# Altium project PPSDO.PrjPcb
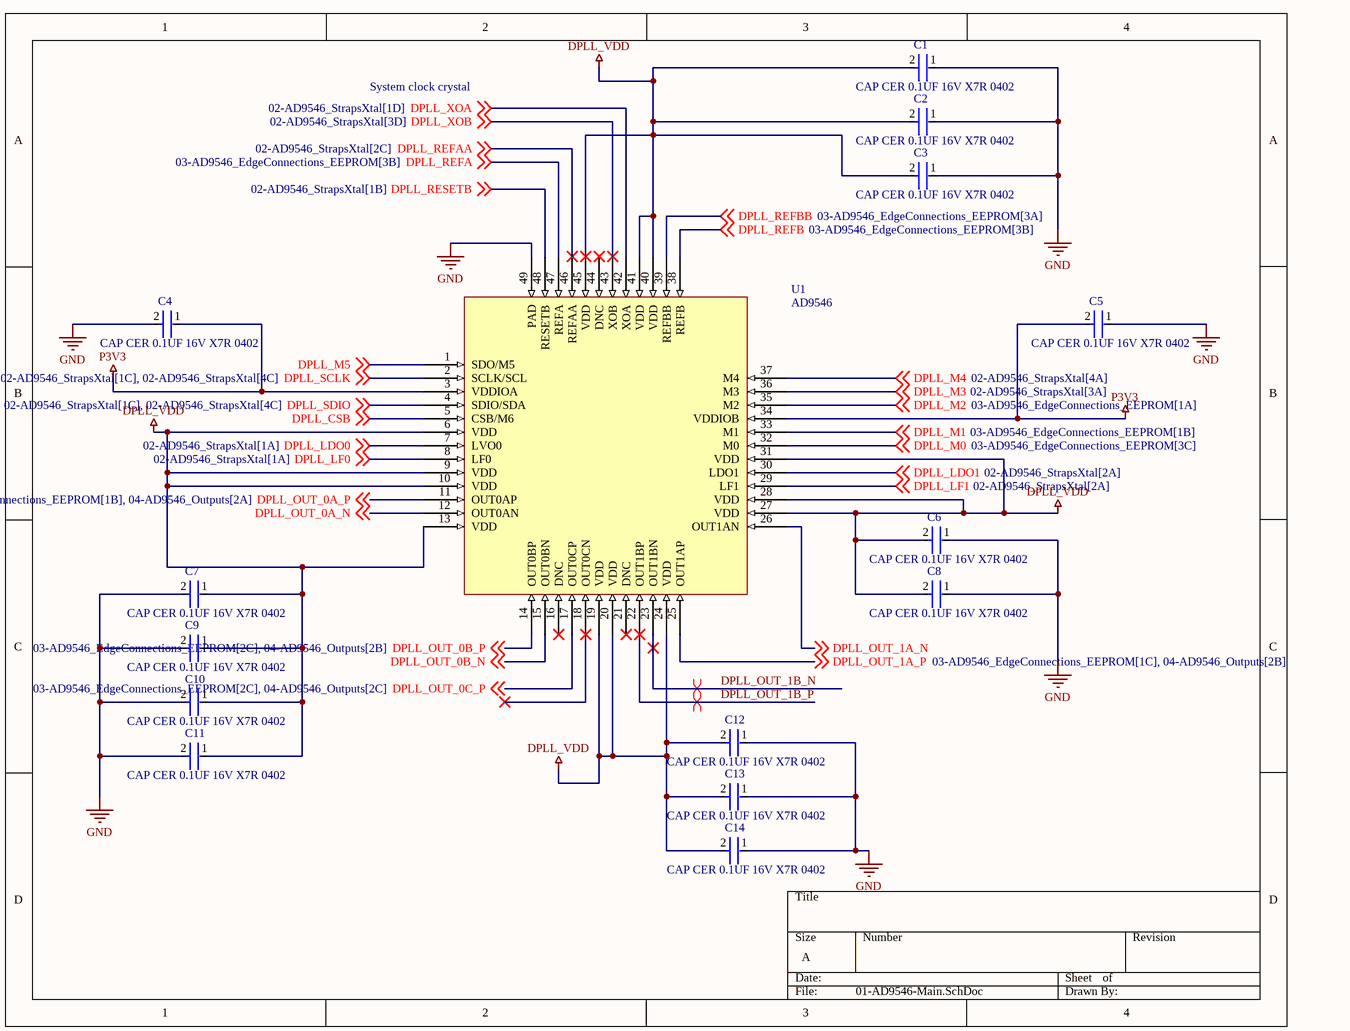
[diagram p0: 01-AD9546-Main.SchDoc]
5 sheets, 66 parts. Net scope: global (net labels, ports and power ports of the same name join across sheets).
Board file: PPSDO.PcbDoc
Sheets:
  01-AD9546-Main.SchDoc
  02-AD9546_StrapsXtal.SchDoc
  03-AD9546_EdgeConnections_EEPROM.SchDoc
  04-AD9546_Outputs.SchDoc
  05-Power.SchDoc

## Sheet 01-AD9546-Main.SchDoc
size A; SheetNumber: 4; SheetTotal: 16

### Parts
C1  GRM155R71C104KA88D  [FP-GRM15-MFG]  (value not drawn)
C2  GRM155R71C104KA88D  [FP-GRM15-MFG]  (value not drawn)
C3  GRM155R71C104KA88D  [FP-GRM15-MFG]  (value not drawn)
C4  GRM155R71C104KA88D  [FP-GRM15-MFG]  (value not drawn)
C5  GRM155R71C104KA88D  [FP-GRM15-MFG]  (value not drawn)
C6  GRM155R71C104KA88D  [FP-GRM15-MFG]  (value not drawn)
C7  GRM155R71C104KA88D  [FP-GRM15-MFG]  (value not drawn)
C8  GRM155R71C104KA88D  [FP-GRM15-MFG]  (value not drawn)
C9  GRM155R71C104KA88D  [FP-GRM15-MFG]  (value not drawn)
C10  GRM155R71C104KA88D  [FP-GRM15-MFG]  (value not drawn)
C11  GRM155R71C104KA88D  [FP-GRM15-MFG]  (value not drawn)
C12  GRM155R71C104KA88D  [FP-GRM15-MFG]  (value not drawn)
C13  GRM155R71C104KA88D  [FP-GRM15-MFG]  (value not drawn)
C14  GRM155R71C104KA88D  [FP-GRM15-MFG]  (value not drawn)
U1  AD9546  [AD9546]

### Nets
DPLL_VDD: C1.2 C2.2 C3.2 C6.2 C7.1 C8.2 C9.1 C10.1 C11.1 C12.2 C13.2 C14.2 U1.6(VDD) U1.9(VDD) U1.10(VDD) U1.13(VDD) U1.19(VDD) U1.20(VDD) U1.24(VDD) U1.27(VDD) U1.28(VDD) U1.31(VDD) U1.40(VDD) U1.41(VDD) U1.45(VDD)
GND: C1.1 C2.1 C3.1 C4.2 C5.1 C6.1 C7.2 C8.1 C9.2 C10.2 C11.2 C12.1 C13.1 C14.1 U1.49(PAD)
P3V3: C4.1 C5.2 U1.3(VDDIOA) U1.34(VDDIOB)
DPLL_CSB: U1.5(CSB/M6) ; off-sheet DPLL_CSB
DPLL_LDO0: U1.7(LVO0) ; off-sheet DPLL_LDO0
DPLL_LDO1: U1.30(LDO1) ; off-sheet DPLL_LDO1
DPLL_LF0: U1.8(LF0) ; off-sheet DPLL_LF0
DPLL_LF1: U1.29(LF1) ; off-sheet DPLL_LF1
DPLL_M0: U1.32(M0) ; off-sheet DPLL_M0
DPLL_M1: U1.33(M1) ; off-sheet DPLL_M1
DPLL_M2: U1.35(M2) ; off-sheet DPLL_M2
DPLL_M3: U1.36(M3) ; off-sheet DPLL_M3
DPLL_M4: U1.37(M4) ; off-sheet DPLL_M4
DPLL_M5: U1.1(SDO/M5) ; off-sheet DPLL_M5
DPLL_OUT_0A_N: U1.12(OUT0AN) ; off-sheet DPLL_OUT_0A_N
DPLL_OUT_0A_P: U1.11(OUT0AP) ; off-sheet DPLL_OUT_0A_P
DPLL_OUT_0B_N: U1.15(OUT0BN) ; off-sheet DPLL_OUT_0B_N
DPLL_OUT_0B_P: U1.14(OUT0BP) ; off-sheet DPLL_OUT_0B_P
DPLL_OUT_0C_P: U1.17(OUT0CP) ; off-sheet DPLL_OUT_0C_P
DPLL_OUT_1A_N: U1.26(OUT1AN) ; off-sheet DPLL_OUT_1A_N
DPLL_OUT_1A_P: U1.25(OUT1AP) ; off-sheet DPLL_OUT_1A_P
DPLL_OUT_1B_N: U1.23(OUT1BN)
DPLL_OUT_1B_P: U1.22(OUT1BP)
DPLL_REFA: U1.47(REFA) ; off-sheet DPLL_REFA
DPLL_REFAA: U1.46(REFAA) ; off-sheet DPLL_REFAA
DPLL_REFB: U1.38(REFB) ; off-sheet DPLL_REFB
DPLL_REFBB: U1.39(REFBB) ; off-sheet DPLL_REFBB
DPLL_RESETB: U1.48(RESETB) ; off-sheet DPLL_RESETB
DPLL_SCLK: U1.2(SCLK/SCL) ; off-sheet DPLL_SCLK
DPLL_SDIO: U1.4(SDIO/SDA) ; off-sheet DPLL_SDIO
DPLL_XOA: U1.42(XOA) ; off-sheet DPLL_XOA
DPLL_XOB: U1.43(XOB) ; off-sheet DPLL_XOB

Not connected (* = marked no-connect by the designer): U1 16(DNC)* 18(OUT0CN)* 21(DNC)* 44(DNC)*

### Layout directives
differential pair; differential pair class 100ohm: DPLL_OUT_1B_N, DPLL_OUT_1B_P

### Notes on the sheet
- System clock crystal

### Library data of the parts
C1-C14 = CMP-2100-03641-2: CAP CER 0.1UF 16V X7R 0402; Manufacturer: Murata; Standoff Height: 0mm; Tolerance: 10%; Voltage Rating: 16Vdc; Material: Ceramic; Capacitance: 0.10μF; Value: 0.10μF

## Sheet 02-AD9546_StrapsXtal.SchDoc
size A; SheetNumber: 5; SheetTotal: 16
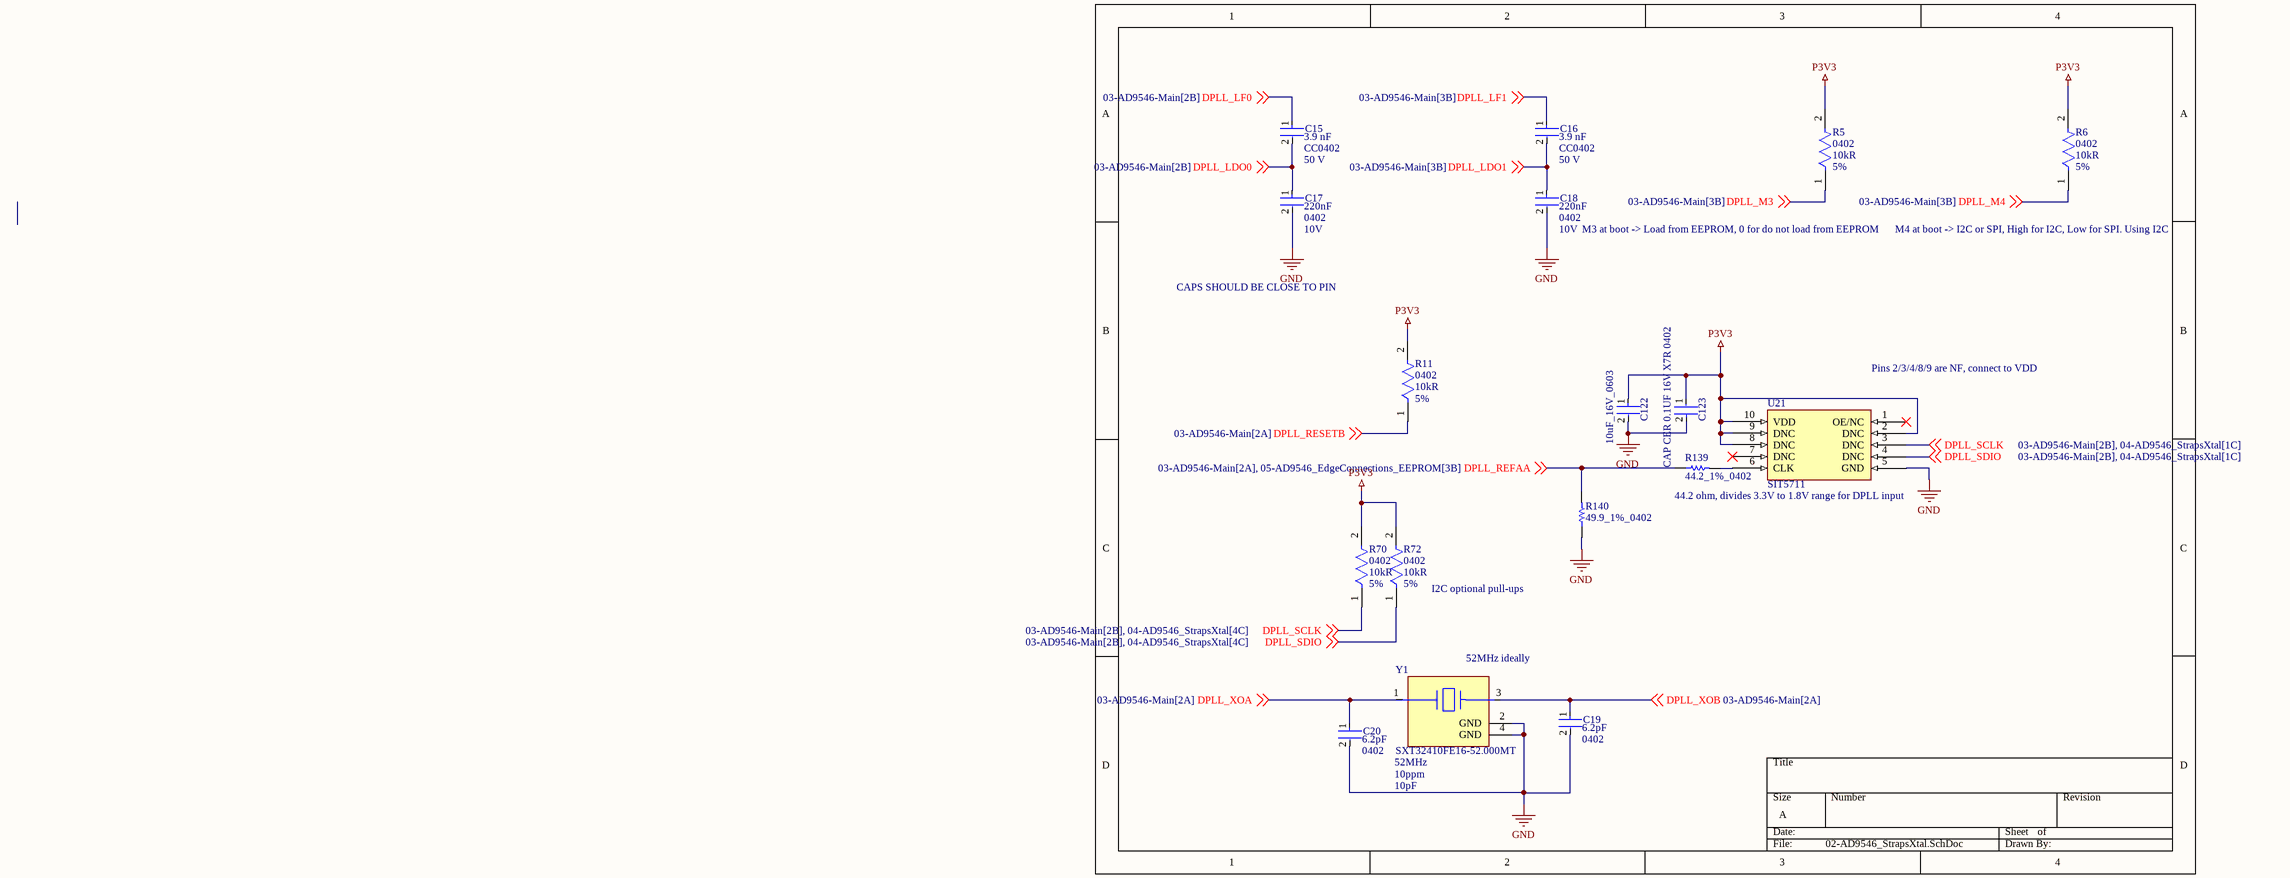
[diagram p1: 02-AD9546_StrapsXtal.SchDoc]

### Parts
C15  value 3.9 nF  Voltage Rating: 50 V  Package: CC0402  [FP-CC0402-MFG]  (hidden comment: CC0402KRX7R9BB392)
C16  value 3.9 nF  Voltage Rating: 50 V  Package: CC0402  [FP-CC0402-MFG]  (hidden comment: CC0402KRX7R9BB392)
C17  Voltage: 10V  Case/Package: 0402  Capacitance: 220nF  [FP-GRM155-0_05-IPC_A]  (hidden comment: GRM155R61A224KE19D)
C18  Voltage: 10V  Case/Package: 0402  Capacitance: 220nF  [FP-GRM155-0_05-IPC_A]  (hidden comment: GRM155R61A224KE19D)
C19  Case/Package: 0402  Capacitance: 6.2pF  [FP-CL468-IPC_C]  (hidden comment: CL05C6R2CB5NNNC)
C20  Case/Package: 0402  Capacitance: 6.2pF  [FP-CL468-IPC_C]  (hidden comment: CL05C6R2CB5NNNC)
C122  10uF_16V_0603  [FP-C1608-MFG]
C123  GRM155R71C104KA88D  [FP-GRM15-MFG]  (value not drawn)
R5  Case/Package: 0402  Resistance: 10kR  Tolerance: 5%  [FP-CRCW0402-e3-IPC_B]  (hidden comment: CRCW040210K0JNED)
R6  Case/Package: 0402  Resistance: 10kR  Tolerance: 5%  [FP-CRCW0402-e3-IPC_B]  (hidden comment: CRCW040210K0JNED)
R11  Case/Package: 0402  Resistance: 10kR  Tolerance: 5%  [FP-CRCW0402-e3-IPC_B]  (hidden comment: CRCW040210K0JNED)
R70  Case/Package: 0402  Resistance: 10kR  Tolerance: 5%  [FP-CRCW0402-e3-IPC_B]  (hidden comment: CRCW040210K0JNED)
R72  Case/Package: 0402  Resistance: 10kR  Tolerance: 5%  [FP-CRCW0402-e3-IPC_B]  (hidden comment: CRCW040210K0JNED)
R139  44.2_1%_0402  [RESC0402(1005)_M]
R140  49.9_1%_0402  [RESC1005X40X25NL05T05]
U21  SIT5711  [SIT5711]
Y1  SXT32410FE16-52.000MT  Frequency: 52MHz  Frequency Stability: 10ppm  Load Capacitance: 10pF  [FP-402-MFG]

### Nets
GND: C17.2 C18.2 C19.2 C20.2 C122.2 C123.2 R140.1 U21.5(GND) Y1.2(GND) Y1.4(GND)
P3V3: C122.1 C123.1 R5.2 R6.2 R11.2 R70.2 R72.2 U21.2(DNC) U21.8(DNC) U21.9(DNC) U21.10(VDD)
DPLL_LDO0: C15.2 C17.1 ; off-sheet DPLL_LDO0
DPLL_LDO1: C16.2 C18.1 ; off-sheet DPLL_LDO1
DPLL_LF0: C15.1 ; off-sheet DPLL_LF0
DPLL_LF1: C16.1 ; off-sheet DPLL_LF1
DPLL_M3: R5.1 ; off-sheet DPLL_M3
DPLL_M4: R6.1 ; off-sheet DPLL_M4
DPLL_REFAA: R139.1 R140.2 ; off-sheet DPLL_REFAA
DPLL_RESETB: R11.1 ; off-sheet DPLL_RESETB
DPLL_SCLK: R70.1 U21.3(DNC) ; off-sheet DPLL_SCLK
DPLL_SDIO: R72.1 U21.4(DNC) ; off-sheet DPLL_SDIO
DPLL_XOA: C20.1 Y1.1 ; off-sheet DPLL_XOA
DPLL_XOB: C19.1 Y1.3 ; off-sheet DPLL_XOB
NetR139_2: R139.2 U21.6(CLK)

Not connected (* = marked no-connect by the designer): U21 1(OE/NC)* 7(DNC)*

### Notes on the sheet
- M3 at boot -> Load from EEPROM, 0 for do not load from EEPROM
- M4 at boot -> I2C or SPI, High for I2C, Low for SPI. Using I2C
- CAPS SHOULD BE CLOSE TO PIN
- Pins 2/3/4/8/9 are NF, connect to VDD
- 44.2 ohm, divides 3.3V to 1.8V range for DPLL input
- (near R72) I2C optional pull-ups
- (near Y1) 52MHz ideally

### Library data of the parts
C15 C16 = CMP-03422-000890-1: CAP CER 3900PF 50V X7R 0402; Manufacturer: YAGEO; Tolerance: 0.1; Temperature Coefficient: 30ppm/°C; Material: Ceramic; Automotive Grade: NA
C17 C18 = CMP-2008-04561-5: CAP CER 0.22UF 10V X5R 0402; Tolerance: 10%; Material: Ceramic; Insulation Resistance: 10GR
C19 C20 = CMP-13271-000420-1: Cap Ceramic 6.2pF 50V C0G ±0.25pF SMD 0402 +125°C Paper T/R
C122 = CMP-08246-000019-1: CAP CER 10UF 16V X5R 0603; Manufacturer: TDK Corporation; Manufacturer Part Number: C1608X5R1C106M080AB; Temperature Coefficient: 15%; Tolerance: 20%; Material: Ceramic
C123 = CMP-2100-03641-2: as C1 on sheet 01-AD9546-Main
R5 R6 R11 R70 R72 = CMP-2002-08136-3: RES Thick Film, 10kΩ, 5%, 0.063W, 200ppm/°C, 0402; Voltage Rating: 50V; Power Rating: 63mW
R139 = CMP-1011-00357-1: 44R2 0.063W 1% 0402 (1005 Metric)  SMD; Case-Metric: 1005; Value: 44.20 Ohm; Case-EIA: 0402
R140 = CMP-2002-00969-1: Manufacturer: Panasonic; Part Number: ERJ-2RKF49R9X
Y1 = CMP-06858-000005-1: CRYSTAL 32.0000MHZ 10PF SMD; Series Resistance: 100R

## Sheet 03-AD9546_EdgeConnections_EEPROM.SchDoc
size A; SheetNumber: 6; SheetTotal: 16
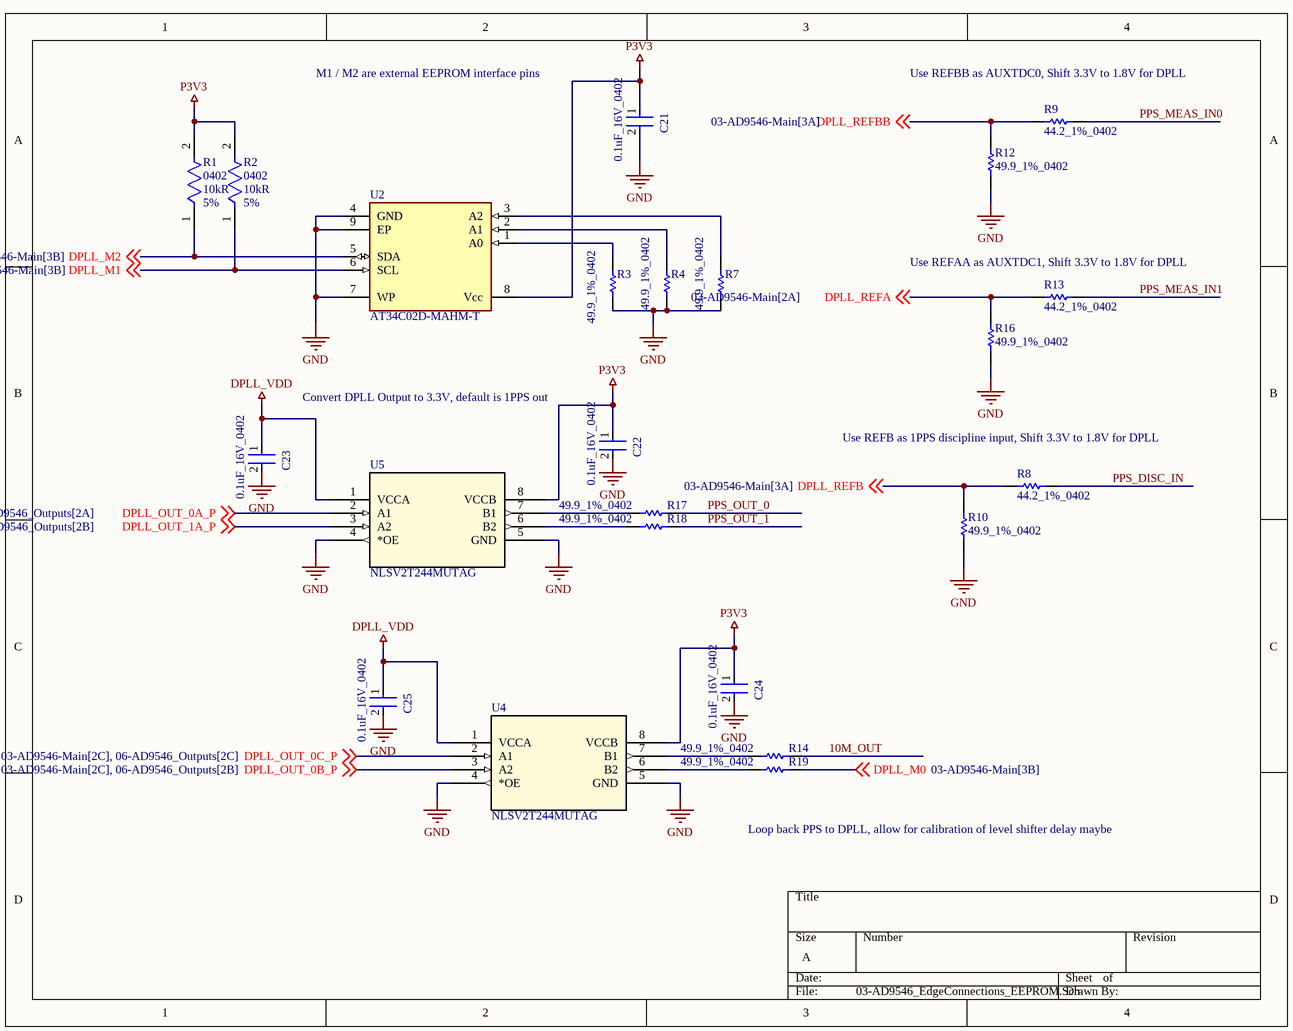
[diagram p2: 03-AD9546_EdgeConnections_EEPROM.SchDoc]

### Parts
C21  0.1uF_16V_0402  [FP-GRM15-MFG]
C22  0.1uF_16V_0402  [FP-GRM15-MFG]
C23  0.1uF_16V_0402  [FP-GRM15-MFG]
C24  0.1uF_16V_0402  [FP-GRM15-MFG]
C25  0.1uF_16V_0402  [FP-GRM15-MFG]
R1  Case/Package: 0402  Resistance: 10kR  Tolerance: 5%  [FP-CRCW0402-e3-IPC_B]  (hidden comment: CRCW040210K0JNED)
R2  Case/Package: 0402  Resistance: 10kR  Tolerance: 5%  [FP-CRCW0402-e3-IPC_B]  (hidden comment: CRCW040210K0JNED)
R3  49.9_1%_0402  [RESC1005X40X25NL05T05]
R4  49.9_1%_0402  [RESC1005X40X25NL05T05]
R7  49.9_1%_0402  [RESC1005X40X25NL05T05]
R8  44.2_1%_0402  [RESC1005X40X25LL05T05]
R9  44.2_1%_0402  [RESC1005X40X25LL05T05]
R10  49.9_1%_0402  [RESC1005X40X25NL05T05]
R12  49.9_1%_0402  [RESC1005X40X25NL05T05]
R13  44.2_1%_0402  [RESC1005X40X25LL05T05]
R14  49.9_1%_0402  [RESC1005X40X25NL05T05]
R16  49.9_1%_0402  [RESC1005X40X25NL05T05]
R17  49.9_1%_0402  [RESC1005X40X25NL05T05]
R18  49.9_1%_0402  [RESC1005X40X25NL05T05]
R19  49.9_1%_0402  [RESC1005X40X25NL05T05]
U2  AT34C02D-MAHM-T  [FP-8MA2-IPC_C]
U4  NLSV2T244MUTAG  [UDFN8_1P20X1P80_ONS]
U5  NLSV2T244MUTAG  [UDFN8_1P20X1P80_ONS]

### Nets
DPLL_VDD: C23.1 C25.1 U4.1(VCCA) U5.1(VCCA)
GND: C21.2 C22.2 C23.2 C24.2 C25.2 R3.1 R4.1 R7.1 R10.1 R12.1 R16.1 U2.4(GND) U2.7(WP) U2.9(EP) U4.4(*OE) U4.5(GND) U5.4(*OE) U5.5(GND)
P3V3: C21.1 C22.1 C24.1 R1.2 R2.2 U2.8(Vcc) U4.8(VCCB) U5.8(VCCB)
10M_OUT: R14.1
DPLL_M0: R19.1 ; off-sheet DPLL_M0
DPLL_M1: R2.1 U2.6(SCL) ; off-sheet DPLL_M1
DPLL_M2: R1.1 U2.5(SDA) ; off-sheet DPLL_M2
DPLL_OUT_0A_P: U5.2(A1) ; off-sheet DPLL_OUT_0A_P
DPLL_OUT_0B_P: U4.3(A2) ; off-sheet DPLL_OUT_0B_P
DPLL_OUT_0C_P: U4.2(A1) ; off-sheet DPLL_OUT_0C_P
DPLL_OUT_1A_P: U5.3(A2) ; off-sheet DPLL_OUT_1A_P
DPLL_REFA: R13.1 R16.2 ; off-sheet DPLL_REFA
DPLL_REFB: R8.1 R10.2 ; off-sheet DPLL_REFB
DPLL_REFBB: R9.1 R12.2 ; off-sheet DPLL_REFBB
PPS_DISC_IN: R8.2
PPS_MEAS_IN0: R9.2
PPS_MEAS_IN1: R13.2
PPS_OUT_0: R17.1
PPS_OUT_1: R18.1
NetR3_2: R3.2 U2.1(A0)
NetR4_2: R4.2 U2.2(A1)
NetR7_2: R7.2 U2.3(A2)
NetR14_2: R14.2 U4.7(B1)
NetR17_2: R17.2 U5.7(B1)
NetR18_2: R18.2 U5.6(B2)
NetR19_2: R19.2 U4.6(B2)

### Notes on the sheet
- M1 / M2 are external EEPROM interface pins
- (near R9) Use REFBB as AUXTDC0, Shift 3.3V to 1.8V for DPLL
- (near R13) Use REFAA as AUXTDC1, Shift 3.3V to 1.8V for DPLL
- Convert DPLL Output to 3.3V, default is 1PPS out
- (near R8) Use REFB as 1PPS discipline input, Shift 3.3V to 1.8V for DPLL
- Loop back PPS to DPLL, allow for calibration of level shifter delay maybe

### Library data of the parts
C21-C25 = CMP-2100-03641-2: CAP CER 0.1UF 16V X7R 0402; Manufacturer Part Number: GRM155R71C104KA88D; Manufacturer: Murata; Standoff Height: 0mm; Tolerance: 10%; Voltage Rating: 16Vdc; Material: Ceramic; Capacitance: 0.10μF; Value: 0.10μF
R1 R2 = CMP-2002-08136-3: as R5 on sheet 02-AD9546_StrapsXtal
R3 R4 R7 R10 R12 R14 R16-R19 = CMP-2002-00969-1: as R140 on sheet 02-AD9546_StrapsXtal
R8 R9 R13 = CMP-2002-00011-1: Manufacturer: Vishay Dale; Part Number: CRCW040244R2FKED
U2 = CMP-06313-000130-1: IC EEPROM 2KBIT I2C 1MHZ 8UDFN
U4 U5 = NLSV2T244MUTAG: No Description Available; Mfr_Name: onsemi

## Sheet 04-AD9546_Outputs.SchDoc
size A; SheetNumber: 7; SheetTotal: 16
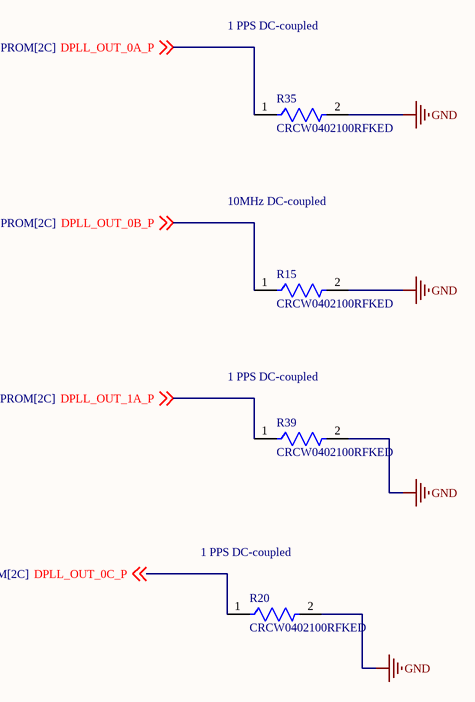
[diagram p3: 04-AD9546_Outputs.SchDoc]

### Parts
R15  CRCW0402100RFKED  [FP-CRCW0402-e3-IPC_C]
R20  CRCW0402100RFKED  [FP-CRCW0402-e3-IPC_C]
R35  CRCW0402100RFKED  [FP-CRCW0402-e3-IPC_C]
R39  CRCW0402100RFKED  [FP-CRCW0402-e3-IPC_C]

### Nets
GND: R15.2 R20.2 R35.2 R39.2
DPLL_OUT_0A_P: R35.1 ; off-sheet DPLL_OUT_0A_P
DPLL_OUT_0B_P: R15.1 ; off-sheet DPLL_OUT_0B_P
DPLL_OUT_0C_P: R20.1 ; off-sheet DPLL_OUT_0C_P
DPLL_OUT_1A_P: R39.1 ; off-sheet DPLL_OUT_1A_P

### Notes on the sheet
- 1 PPS DC-coupled
- 10MHz DC-coupled

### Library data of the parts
R15 R20 R35 R39 = CMP-1011-00397-3: RES Thick Film, 100Ω, 1%, 0.063W, 100ppm/°C, 0402; Max Power Dissipation: 63mW; Voltage Rating: 50V; Resistance: 100R

## Sheet 05-Power.SchDoc
size A; SheetNumber: 16; SheetTotal: 16
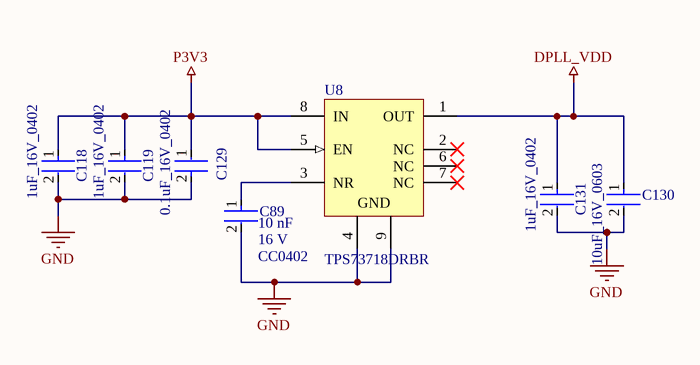
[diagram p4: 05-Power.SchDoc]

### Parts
C89  value 10 nF  Package: CC0402  Voltage Rating: 16 V  [FP-CC0402-MFG]  (hidden comment: CC0402KRX7R7BB103)
C118  1uF_16V_0402  [FP-0402-L_1_0_0_05-W_0_5-IPC_C]
C119  1uF_16V_0402  [FP-0402-L_1_0_0_05-W_0_5-IPC_C]
C129  0.1uF_16V_0402  [FP-GRM15-MFG]
C130  10uF_16V_0603  [FP-MK107BA-IPC_A]
C131  1uF_16V_0402  [FP-0402-L_1_0_0_05-W_0_5-IPC_C]
U8  TPS73718DRBR  [DRB0008A_V]

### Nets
DPLL_VDD: C130.1 C131.1 U8.1(OUT)
GND: C89.2 C118.2 C119.2 C129.2 C130.2 C131.2 U8.4(GND) U8.9(GND)
P3V3: C118.1 C119.1 C129.1 U8.5(EN) U8.8(IN)
NetC89_1: C89.1 U8.3(NR)

Not connected (* = marked no-connect by the designer): U8 2(NC)* 6(NC)* 7(NC)*

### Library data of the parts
C89 = CMP-03422-000501-1: CAP CER 10000PF 16V X7R 0402; Manufacturer: YAGEO; Automotive Grade: NA; Material: Ceramic; Tolerance: 0.1; Temperature Coefficient: 30ppm/°C
C118 C119 C131 = CMP-14477-003537-2: None; Tolerance: 20%; Voltage Rating (DC): 16V; Capacitance: 1uF; Dielectric: X5R
C129 = CMP-2100-03641-2: as C21 on sheet 03-AD9546_EdgeConnections_EEPROM
C130 = CMP-2000-06226-3: None; Dielectric: X5R; Voltage Rating: 16V; Tolerance: 20%; Capacitance: 10uF
U8 = CMP-0395-00613-2: Single Output LDO, 1 A, Fixed 1.8 V Output, 2.2 to 5.5 V Input, with Reverse Current Protection, 8-pin SON (DRB), -40 to 125 degC, Green (RoHS & no Sb/Br); Manufacturer: Texas Instruments; Fixed Output Options(V): 1.8; Vin(Min)(V): 2.2; Iq(Typ)(mA): 0.3; Accuracy(%): 3; Vdo(Typ)(mV): 130; SubFamily: Single Channel LDO; Vin(Max)(V): 5.5; Iout(Max)(A): 1; Rating: Catalog

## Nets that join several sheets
DPLL_VDD: 01-AD9546-Main (25 pins), 03-AD9546_EdgeConnections_EEPROM (C23.1 C25.1 U4.1 U5.1), 05-Power (C130.1 C131.1 U8.1)
GND: 01-AD9546-Main (15 pins), 02-AD9546_StrapsXtal (10 pins), 03-AD9546_EdgeConnections_EEPROM (18 pins), 04-AD9546_Outputs (R15.2 R20.2 R35.2 R39.2), 05-Power (8 pins)
P3V3: 01-AD9546-Main (C4.1 C5.2 U1.3 U1.34), 02-AD9546_StrapsXtal (11 pins), 03-AD9546_EdgeConnections_EEPROM (8 pins), 05-Power (5 pins)
DPLL_LDO0: 01-AD9546-Main (U1.7), 02-AD9546_StrapsXtal (C15.2 C17.1)
DPLL_LDO1: 01-AD9546-Main (U1.30), 02-AD9546_StrapsXtal (C16.2 C18.1)
DPLL_LF0: 01-AD9546-Main (U1.8), 02-AD9546_StrapsXtal (C15.1)
DPLL_LF1: 01-AD9546-Main (U1.29), 02-AD9546_StrapsXtal (C16.1)
DPLL_M0: 01-AD9546-Main (U1.32), 03-AD9546_EdgeConnections_EEPROM (R19.1)
DPLL_M1: 01-AD9546-Main (U1.33), 03-AD9546_EdgeConnections_EEPROM (R2.1 U2.6)
DPLL_M2: 01-AD9546-Main (U1.35), 03-AD9546_EdgeConnections_EEPROM (R1.1 U2.5)
DPLL_M3: 01-AD9546-Main (U1.36), 02-AD9546_StrapsXtal (R5.1)
DPLL_M4: 01-AD9546-Main (U1.37), 02-AD9546_StrapsXtal (R6.1)
DPLL_OUT_0A_P: 01-AD9546-Main (U1.11), 03-AD9546_EdgeConnections_EEPROM (U5.2), 04-AD9546_Outputs (R35.1)
DPLL_OUT_0B_P: 01-AD9546-Main (U1.14), 03-AD9546_EdgeConnections_EEPROM (U4.3), 04-AD9546_Outputs (R15.1)
DPLL_OUT_0C_P: 01-AD9546-Main (U1.17), 03-AD9546_EdgeConnections_EEPROM (U4.2), 04-AD9546_Outputs (R20.1)
DPLL_OUT_1A_P: 01-AD9546-Main (U1.25), 03-AD9546_EdgeConnections_EEPROM (U5.3), 04-AD9546_Outputs (R39.1)
DPLL_REFA: 01-AD9546-Main (U1.47), 03-AD9546_EdgeConnections_EEPROM (R13.1 R16.2)
DPLL_REFAA: 01-AD9546-Main (U1.46), 02-AD9546_StrapsXtal (R139.1 R140.2)
DPLL_REFB: 01-AD9546-Main (U1.38), 03-AD9546_EdgeConnections_EEPROM (R8.1 R10.2)
DPLL_REFBB: 01-AD9546-Main (U1.39), 03-AD9546_EdgeConnections_EEPROM (R9.1 R12.2)
DPLL_RESETB: 01-AD9546-Main (U1.48), 02-AD9546_StrapsXtal (R11.1)
DPLL_SCLK: 01-AD9546-Main (U1.2), 02-AD9546_StrapsXtal (R70.1 U21.3)
DPLL_SDIO: 01-AD9546-Main (U1.4), 02-AD9546_StrapsXtal (R72.1 U21.4)
DPLL_XOA: 01-AD9546-Main (U1.42), 02-AD9546_StrapsXtal (C20.1 Y1.1)
DPLL_XOB: 01-AD9546-Main (U1.43), 02-AD9546_StrapsXtal (C19.1 Y1.3)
